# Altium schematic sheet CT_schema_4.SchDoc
size 218 x 258 mm
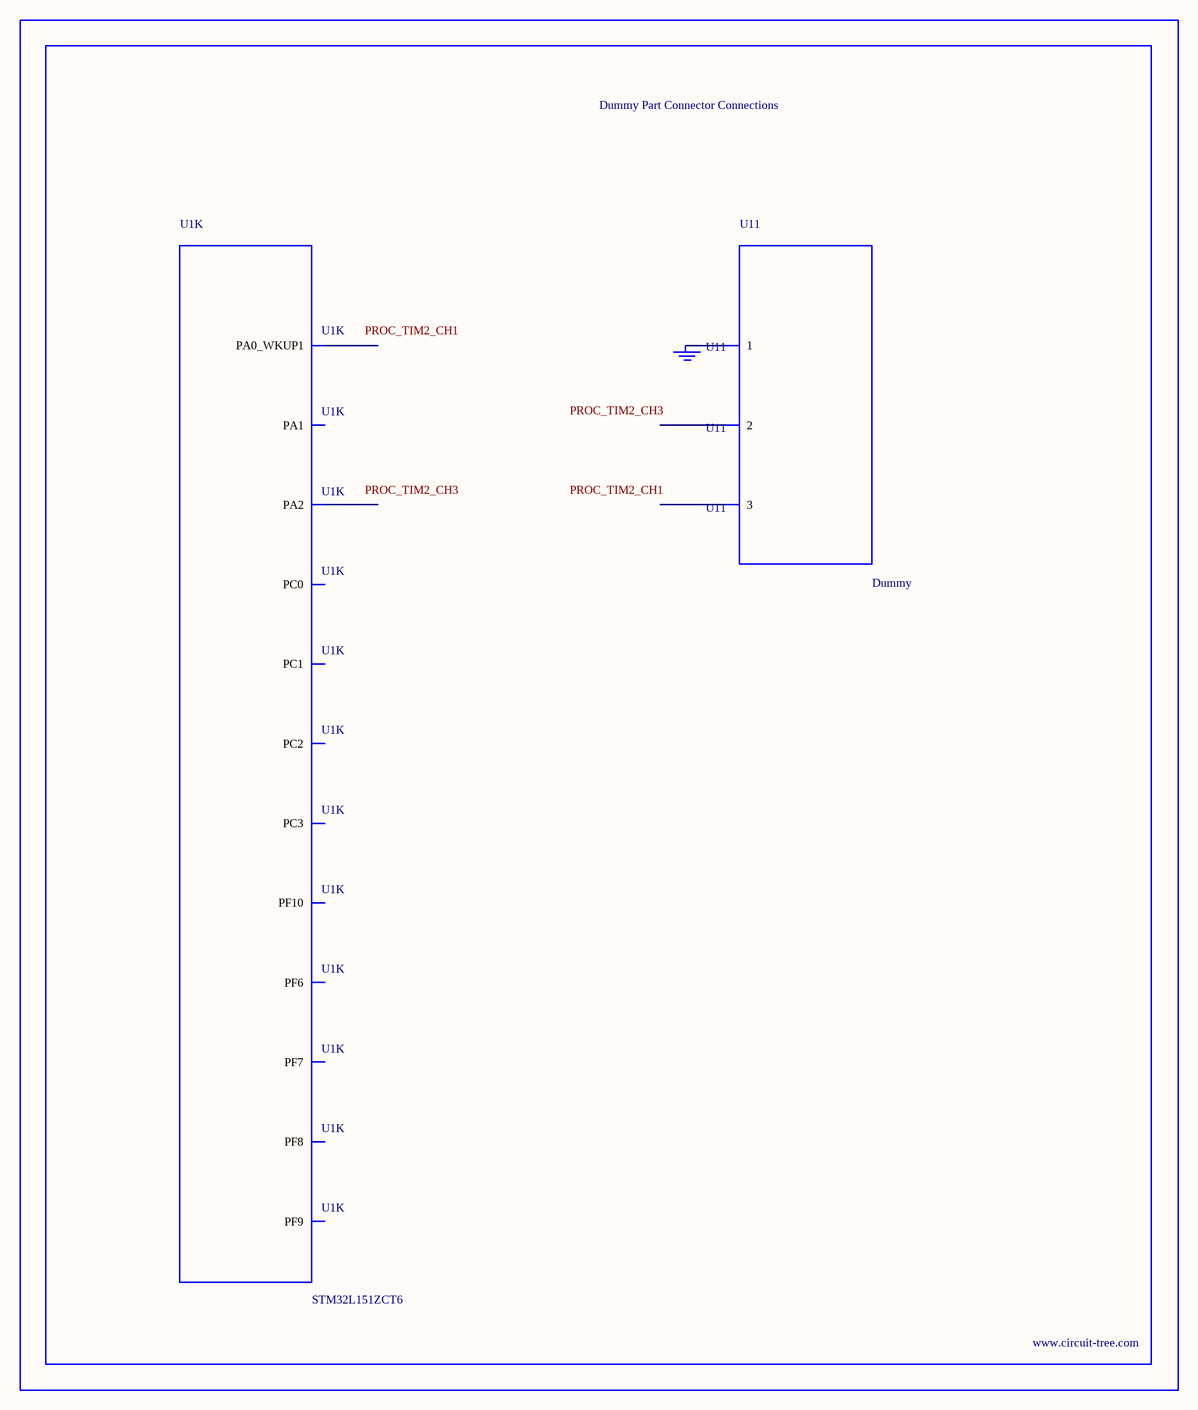
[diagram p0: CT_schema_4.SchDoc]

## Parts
BORDER3  (no value)
GND_INSTANCE_3_0  (no value)
U1  STM32L151ZCT6  [LQFP144]  (part K of 11)
U11  Dummy  [DUMMY_PACKAGE_122]

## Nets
NetGND_INSTANCE_3_0_0: GND_INSTANCE_3_0.0(GND) U11.1

Not connected (* = marked no-connect by the designer): U1 18(PF6) 19(PF7) 20(PF8) 21(PF9) 22(PF10) 26(PC0) 27(PC1) 28(PC2) 29(PC3) 34(PA0_WKUP1) 35(PA1) 36(PA2); U11 2 3

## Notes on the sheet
- Labels drawn without touching a wire or pin: PROC_TIM2_CH1, PROC_TIM2_CH3

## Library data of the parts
BORDER3 = BORDER_PAGE3
GND_INSTANCE_3_0 = GND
